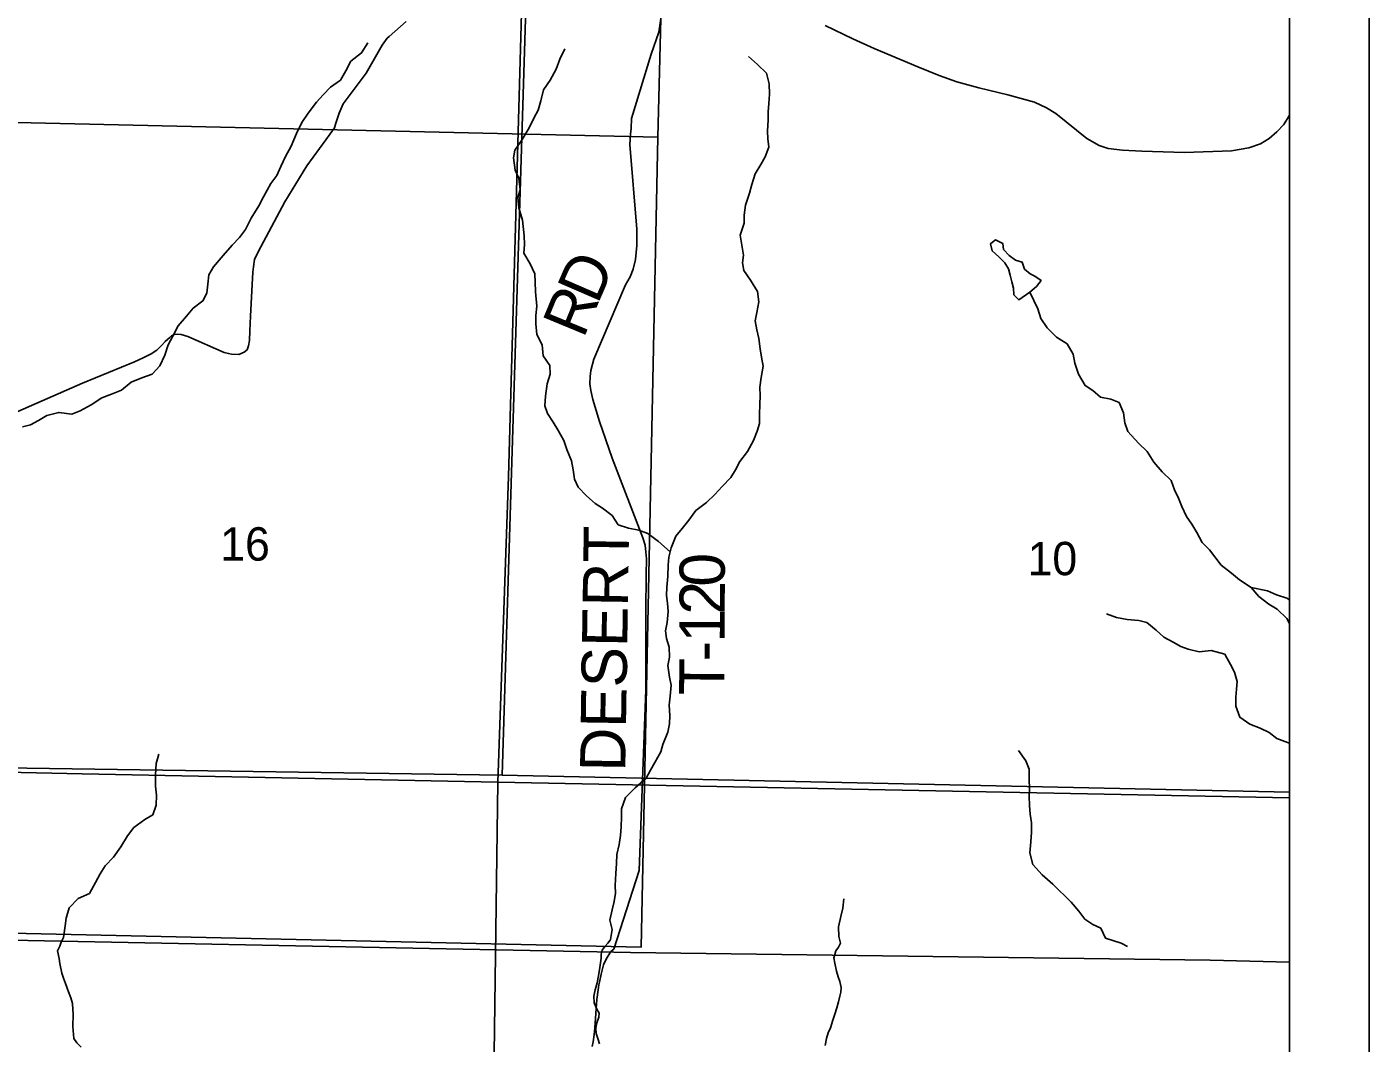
# Model space of a CAD drawing. Extents: x -19.9 to 41.9, y 0 to 32.3.
# Drawn here: x 7.317 to 9, y 17.59 to 18.865 of the extents above; entities that cross this region are included whole.
import ezdxf

# ---------------------------------------------------------------- set-up
doc = ezdxf.new("R2010")
doc.units = 0
for name, color, linetype in [('GM_X_Corporation', 7, 'Continuous'), ('GM_X_County', 7, 'Continuous'), ('GM_X_Minor_Lake', 7, 'Continuous'), ('GM_X_Minor_River', 7, 'Continuous'), ('GM_X_Section', 7, 'Continuous'), ('GM_X_Section_Text', 7, 'Continuous'), ('GM_X_State_Route', 7, 'Continuous'), ('GM_X_Township_Road', 7, 'Continuous'), ('GM_X_Township_Road_Text', 7, 'Continuous'), ('SH_Data', 7, 'Continuous')]:
    doc.layers.add(name, color=color, linetype=linetype)

msp = doc.modelspace()

# ---------------------------------------------------------------- linework, layer by layer
at = {"layer": 'GM_X_Corporation'}
for points in [[(8.9, 17.8974), (8.9, 20.9), (2.1, 20.9), (2.1, 17.918), (2.4715, 17.9106), (2.973, 17.9007), (3.7505, 17.884), (3.984, 17.879), (4.2613, 17.8672), (4.9169, 17.8392), (5.0192, 17.8403), (5.0257, 17.9637), (5.4954, 17.9559), (5.761, 17.9543), (5.9048, 17.9534), (6.2397, 17.9517), (6.2497, 17.9517), (6.3069, 17.9505), (6.7, 17.9422), (6.9468, 17.937), (7.3858, 17.9277), (7.5529, 17.9242), (7.9072, 17.9171)], [(8.9, 17.8974), (8.9, 20.9), (7.9833, 20.9), (7.9567, 19.9408), (7.9433, 19.1981), (7.9387, 18.9418), (7.9208, 18.3004), (7.9072, 17.9171)], [(6.9135, 18.9637), (7.944, 18.9426), (7.9129, 17.9261), (6.8905, 17.9411)], [(8.9, 17.9044), (8.9, 18.9209), (7.944, 18.9426), (7.9129, 17.9261)], [(2.1, 17.918), (2.1, 14.1), (8.9, 14.1), (8.9, 17.8974), (7.9072, 17.9171), (7.5529, 17.9242), (7.3858, 17.9277), (6.9468, 17.937), (6.7, 17.9422), (6.3069, 17.9505), (6.2497, 17.9517), (6.2397, 17.9517), (5.9048, 17.9534), (5.761, 17.9543), (5.4954, 17.9559), (5.0257, 17.9637), (5.0192, 17.8403), (4.9169, 17.8392), (4.2613, 17.8672), (3.984, 17.879), (3.7505, 17.884), (2.973, 17.9007), (2.4715, 17.9106)], [(7.8246, 14.1), (8.9, 14.1), (8.9, 17.8974), (7.9072, 17.9171), (7.9012, 17.4524), (7.8776, 16.5173), (7.8702, 16.1679), (7.854, 15.4058), (7.8518, 15.3043)]]:
    msp.add_lwpolyline(points, close=True, dxfattribs=at)
for points in [[(2.973, 17.9007), (3.7505, 17.884), (3.984, 17.879), (4.2613, 17.8672), (4.9169, 17.8392), (5.0192, 17.8403), (5.0257, 17.9637), (5.4954, 17.9559), (5.761, 17.9543), (5.9048, 17.9534), (6.2397, 17.9517), (6.2497, 17.9517), (6.3069, 17.9505), (6.7, 17.9422), (6.9468, 17.937), (7.3858, 17.9277), (7.5529, 17.9242), (7.9072, 17.9171), (7.9208, 18.3004), (7.9387, 18.9418), (7.9433, 19.1981), (7.9567, 19.9408), (7.9833, 20.9), (2.1, 20.9)], [(7.9012, 17.4524), (7.9072, 17.9171), (7.5529, 17.9242), (7.3858, 17.9277), (6.9468, 17.937), (6.7, 17.9422), (6.3069, 17.9505), (6.2497, 17.9517), (6.2397, 17.9517), (5.9048, 17.9534), (5.761, 17.9543), (5.4954, 17.9559), (5.0257, 17.9637), (5.0192, 17.8403), (4.9169, 17.8392), (4.2613, 17.8672), (3.984, 17.879), (3.7505, 17.884), (2.973, 17.9007), (2.4715, 17.9106), (2.1, 17.918), (2.1, 14.1)]]:
    msp.add_lwpolyline(points, dxfattribs=at)
at = {"layer": 'GM_X_County'}
msp.add_lwpolyline([(8.9, 17.6915), (8.8006, 17.694), (8.0736, 17.7036), (7.0652, 17.7237), (6.7109, 17.7307), (6.5438, 17.7343), (6.1048, 17.7436), (5.8581, 17.7488), (5.4649, 17.757), (5.4078, 17.7582), (5.3977, 17.7582), (5.0628, 17.7599), (4.9191, 17.7608), (4.6534, 17.7624), (4.1838, 17.7703), (4.1772, 17.6468), (4.0749, 17.6457), (3.4193, 17.6737), (3.142, 17.6855), (2.9085, 17.6906), (2.1311, 17.7073), (2.1, 17.7079)], dxfattribs=at)
at = {"layer": 'GM_X_Minor_Lake'}
for points in [[(8.5276, 18.5943), (8.5252, 18.5924), (8.5272, 18.5837), (8.5356, 18.5761), (8.5429, 18.5686), (8.5475, 18.561), (8.5498, 18.5531), (8.5518, 18.5448), (8.5538, 18.5368), (8.5546, 18.5285), (8.5607, 18.5221), (8.5743, 18.5317)], [(8.5743, 18.5317), (8.583, 18.539), (8.5886, 18.5462), (8.5806, 18.5518), (8.5749, 18.5548), (8.5676, 18.5608), (8.5649, 18.5696), (8.5565, 18.5718), (8.5485, 18.5778), (8.5416, 18.5853), (8.5404, 18.5929), (8.5316, 18.5974), (8.5276, 18.5943)], [(8.852, 18.1613), (8.8617, 18.15), (8.8743, 18.1404), (8.8847, 18.1341), (8.8966, 18.1226), (8.9, 18.116)], [(8.9, 18.1458), (8.8969, 18.148), (8.884, 18.152), (8.8725, 18.1571), (8.852, 18.1613)]]:
    msp.add_lwpolyline(points, dxfattribs=at)
at = {"layer": 'GM_X_Minor_River'}
for points in [[(7.3112, 18.3628), (7.3211, 18.3655), (7.3313, 18.3709), (7.3415, 18.3771), (7.3567, 18.381), (7.373, 18.3789), (7.3836, 18.3828), (7.3972, 18.3905), (7.4108, 18.3993), (7.4229, 18.404), (7.4354, 18.4087), (7.4475, 18.419), (7.4608, 18.4241), (7.4736, 18.4291), (7.4834, 18.4394), (7.4898, 18.4528), (7.4938, 18.4657), (7.4998, 18.4764), (7.5062, 18.4894), (7.5167, 18.5016), (7.525, 18.5116), (7.5374, 18.5208), (7.5423, 18.5307), (7.5434, 18.5417), (7.5448, 18.5535), (7.5508, 18.5634), (7.5628, 18.5776), (7.5741, 18.5906), (7.5835, 18.6002), (7.591, 18.6105), (7.5981, 18.6246), (7.6075, 18.6402), (7.6135, 18.6513), (7.6228, 18.6681), (7.6303, 18.678), (7.6352, 18.6894), (7.6411, 18.702), (7.6479, 18.715), (7.6546, 18.7306), (7.6613, 18.7447), (7.6696, 18.7565), (7.6797, 18.7699), (7.6884, 18.7795), (7.6974, 18.7891), (7.7099, 18.7975), (7.7166, 18.8093), (7.7229, 18.8215), (7.7365, 18.8319), (7.7444, 18.8445)], [(8.1233, 18.2059), (8.1086, 18.2189), (8.0956, 18.2291), (8.0841, 18.2331), (8.0712, 18.2357), (8.0582, 18.2401), (8.0506, 18.2515), (8.0387, 18.2608), (8.0292, 18.2665), (8.0184, 18.2762), (8.0081, 18.2872), (8.0035, 18.297), (8.0018, 18.3088), (7.9995, 18.3201), (7.9937, 18.3345), (7.9901, 18.3455), (7.9824, 18.3591), (7.9767, 18.3689), (7.9697, 18.3795), (7.9662, 18.3893), (7.9669, 18.4015), (7.969, 18.4167), (7.9731, 18.4289), (7.9727, 18.4399), (7.9642, 18.452), (7.9629, 18.4656), (7.956, 18.4788), (7.9551, 18.4921), (7.955, 18.5024), (7.9561, 18.5142), (7.9544, 18.532), (7.9539, 18.5445), (7.9535, 18.5548), (7.948, 18.5672), (7.94, 18.5808), (7.9406, 18.5915), (7.9405, 18.6025), (7.9381, 18.6222), (7.9338, 18.6374), (7.9325, 18.6506), (7.9355, 18.6602), (7.9335, 18.6746), (7.9292, 18.6848), (7.9268, 18.7003), (7.9286, 18.7098), (7.938, 18.7232), (7.9466, 18.7377), (7.9526, 18.7499), (7.9578, 18.7602), (7.9612, 18.7716), (7.9645, 18.7857), (7.9731, 18.7975), (7.9806, 18.8113), (7.985, 18.8242), (7.9914, 18.8368)], [(8.0483, 17.719), (8.0485, 17.7199), (8.0506, 17.7323), (8.0479, 17.7441), (8.0508, 17.757), (8.053, 17.7673), (8.0548, 17.7779), (8.0544, 17.7874), (8.0554, 17.8026), (8.056, 17.8152), (8.0567, 17.8262), (8.0596, 17.8391), (8.0611, 17.8501), (8.0621, 17.8612), (8.0624, 17.8737), (8.0623, 17.8836), (8.0675, 17.898), (8.0796, 17.9099), (8.0931, 17.9222), (8.0987, 17.9321), (8.104, 17.942), (8.1115, 17.955), (8.1141, 17.9645), (8.1204, 17.9798), (8.1226, 17.9904), (8.1229, 18.0007), (8.122, 18.0136), (8.1234, 18.025), (8.1245, 18.039), (8.1225, 18.0489), (8.1205, 18.0633), (8.1227, 18.074), (8.1222, 18.0865), (8.119, 18.0975), (8.1174, 18.107), (8.1196, 18.1172), (8.121, 18.1313), (8.1202, 18.1415), (8.119, 18.1514), (8.1193, 18.1617), (8.1203, 18.1757), (8.121, 18.1894), (8.1216, 18.1993), (8.1246, 18.2111), (8.1305, 18.2256), (8.1384, 18.2355), (8.1467, 18.2458), (8.1557, 18.2577), (8.1689, 18.268), (8.1795, 18.278), (8.1885, 18.288), (8.1994, 18.2991), (8.2054, 18.309), (8.2107, 18.3193), (8.2204, 18.3319), (8.2279, 18.3456), (8.2324, 18.3575), (8.2353, 18.367), (8.2356, 18.378), (8.2359, 18.3913), (8.2362, 18.4019), (8.2357, 18.4125), (8.2375, 18.4247), (8.2401, 18.4388), (8.2381, 18.4502), (8.2361, 18.4608), (8.2345, 18.4737), (8.2321, 18.4847), (8.2301, 18.496), (8.2323, 18.5063), (8.2348, 18.5196), (8.2328, 18.5325), (8.224, 18.5469), (8.2159, 18.5589), (8.2143, 18.5684), (8.2154, 18.5783), (8.2134, 18.5908), (8.211, 18.6033), (8.2162, 18.6185), (8.2161, 18.6284), (8.2179, 18.641), (8.2227, 18.6558), (8.226, 18.6668), (8.2301, 18.6802), (8.2372, 18.692), (8.2424, 18.7015), (8.2473, 18.7137), (8.2457, 18.7243), (8.2456, 18.7338), (8.2462, 18.7479), (8.2465, 18.7581), (8.2472, 18.7684), (8.2479, 18.7802), (8.2474, 18.7931), (8.2442, 18.8063), (8.2331, 18.8172), (8.2216, 18.8274)], [(8.7998, 18.2086), (8.7907, 18.2176), (8.7838, 18.2304), (8.7776, 18.2406), (8.7711, 18.2505), (8.7649, 18.2629), (8.7607, 18.2732), (8.756, 18.2837), (8.7517, 18.2955), (8.7403, 18.3064), (8.7299, 18.3185), (8.7218, 18.3317), (8.7107, 18.3422), (8.6973, 18.3569), (8.6934, 18.3679), (8.6918, 18.3804), (8.6864, 18.3933), (8.6761, 18.3977), (8.6631, 18.3999), (8.6536, 18.4086), (8.644, 18.4146), (8.6356, 18.4289), (8.6309, 18.4425), (8.6289, 18.4539), (8.6212, 18.4671), (8.6078, 18.4754), (8.5963, 18.487), (8.5883, 18.4987), (8.5847, 18.5109), (8.5743, 18.5317)], [(8.9, 18.116), (8.8966, 18.1226), (8.8847, 18.1341), (8.8743, 18.1404), (8.8617, 18.15), (8.852, 18.1613), (8.8375, 18.1709), (8.8275, 18.1794), (8.8145, 18.1895), (8.7998, 18.2086)], [(8.8017, 18.0821), (8.7869, 18.0808), (8.7732, 18.0841), (8.7637, 18.0871), (8.7542, 18.0927), (8.7427, 18.0991), (8.7328, 18.1077), (8.7213, 18.1175), (8.711, 18.1201), (8.6966, 18.1211), (8.6833, 18.1236), (8.6707, 18.1284)], [(8.9, 17.9661), (8.8977, 17.967), (8.8843, 17.9721), (8.8744, 17.9795), (8.8633, 17.985), (8.8503, 17.9897), (8.8377, 17.9986), (8.8326, 18.0126), (8.8327, 18.0236), (8.8337, 18.0338), (8.8343, 18.0433), (8.8311, 18.055), (8.826, 18.0648), (8.819, 18.0776), (8.8017, 18.0821)], [(7.3625, 17.7222), (7.3647, 17.7371), (7.3661, 17.7466), (7.3698, 17.7595), (7.3811, 17.771), (7.3951, 17.7776), (7.4029, 17.7913), (7.4086, 17.802), (7.4149, 17.8123), (7.4251, 17.823), (7.4345, 17.836), (7.4427, 17.8498), (7.4506, 17.8601), (7.4646, 17.8705), (7.4748, 17.8763), (7.4789, 17.8881), (7.4791, 17.901), (7.4779, 17.912), (7.4778, 17.9264), (7.4788, 17.9405), (7.4821, 17.9523)], [(8.6968, 17.7109), (8.6892, 17.7151), (8.6695, 17.7213), (8.6633, 17.7338), (8.6534, 17.7387), (8.6434, 17.7454), (8.6358, 17.7552), (8.6262, 17.7665), (8.6032, 17.7891), (8.5898, 17.8008), (8.5783, 17.814), (8.5744, 17.8284), (8.5758, 17.8424), (8.5764, 17.8542), (8.5767, 17.866), (8.5747, 17.877), (8.5739, 17.888), (8.5738, 17.8997), (8.5741, 17.9096), (8.5736, 17.9202), (8.5735, 17.9335), (8.5693, 17.9438), (8.5604, 17.957)], [(8.337, 17.7153), (8.3348, 17.7234), (8.3347, 17.7355), (8.3376, 17.7485), (8.3398, 17.7591), (8.3413, 17.7709)], [(7.3626, 17.6711), (7.3606, 17.6775), (7.3578, 17.6897), (7.357, 17.6958), (7.3549, 17.7056), (7.3578, 17.7112), (7.3596, 17.7165), (7.3625, 17.7222)], [(8.0347, 17.5887), (8.0331, 17.5944), (8.0307, 17.602), (8.0302, 17.6085), (8.0316, 17.6153), (8.0338, 17.6222), (8.0345, 17.6272), (8.0314, 17.6325), (8.0283, 17.6404), (8.0278, 17.6488), (8.0292, 17.6568), (8.0317, 17.6656), (8.0335, 17.674), (8.0352, 17.6847), (8.0369, 17.6962), (8.0369, 17.7015), (8.0383, 17.7065), (8.0414, 17.7111), (8.0453, 17.7153), (8.0483, 17.719)], [(8.3179, 17.5866), (8.3193, 17.5957), (8.3215, 17.6026), (8.3244, 17.6091), (8.3273, 17.6187), (8.3298, 17.626), (8.3324, 17.634), (8.3345, 17.6417), (8.3363, 17.6485), (8.3374, 17.6539), (8.3377, 17.6596), (8.3361, 17.6672), (8.3341, 17.6729), (8.3321, 17.6801), (8.3301, 17.69), (8.3285, 17.6968), (8.3301, 17.7009), (8.331, 17.7054), (8.3344, 17.7101), (8.337, 17.7153)], [(7.3846, 17.5849), (7.3793, 17.5902), (7.3754, 17.5955), (7.3744, 17.6107), (7.3746, 17.6256), (7.3737, 17.6393), (7.3717, 17.6465), (7.3689, 17.654), (7.365, 17.6646), (7.3626, 17.6711)]]:
    msp.add_lwpolyline(points, dxfattribs=at)
at = {"layer": 'GM_X_Section'}
for points in [[(7.1171, 19.7458), (8.1335, 19.7322), (8.1079, 18.7263), (7.1021, 18.7492)], [(7.1021, 18.7492), (8.1079, 18.7263), (8.0871, 17.7103), (7.0709, 17.7326)]]:
    msp.add_lwpolyline(points, close=True, dxfattribs=at)
at = {"layer": 'GM_X_State_Route'}
msp.add_lwpolyline([(8.3176, 18.8663), (8.3524, 18.8495), (8.3791, 18.8374), (8.4339, 18.8146), (8.4609, 18.8036), (8.4828, 18.7957), (8.5106, 18.7879), (8.5469, 18.7791), (8.5804, 18.7702), (8.5954, 18.763), (8.6069, 18.7559), (8.6459, 18.7246), (8.6615, 18.7159), (8.6729, 18.712), (8.6908, 18.7099), (8.715, 18.7088), (8.7685, 18.707), (8.8272, 18.709), (8.8491, 18.713), (8.8636, 18.7177), (8.8744, 18.7244), (8.8844, 18.7327), (8.8932, 18.7422), (8.9, 18.7539)], dxfattribs=at)
at = {"layer": 'GM_X_Township_Road'}
for points in [[(7.292, 18.3762), (7.3866, 18.4176), (7.4516, 18.4443), (7.4627, 18.4494), (7.4725, 18.4543), (7.4797, 18.4592), (7.4862, 18.4656), (7.4899, 18.4699), (7.4936, 18.4727), (7.4958, 18.4749), (7.4982, 18.477), (7.5012, 18.4786), (7.5057, 18.4792), (7.5103, 18.4788), (7.5186, 18.476), (7.564, 18.4562), (7.5695, 18.4548), (7.5732, 18.4541), (7.5825, 18.4535), (7.5891, 18.4564), (7.5928, 18.4596), (7.5947, 18.4643), (7.5958, 18.4712), (7.5963, 18.4834), (7.5973, 18.5016), (7.5992, 18.5414), (7.5999, 18.557), (7.6008, 18.5634), (7.6022, 18.5726), (7.6055, 18.5797), (7.61, 18.5887), (7.6401, 18.6449), (7.6678, 18.6903), (7.6916, 18.7228), (7.7023, 18.738), (7.7043, 18.7438), (7.7085, 18.7564), (7.7135, 18.7678), (7.7422, 18.8065), (7.7622, 18.8415), (7.7685, 18.8503), (7.7709, 18.8526), (7.7923, 18.8711)], [(8.1128, 18.8832), (8.1091, 18.858), (8.0995, 18.8302), (8.0748, 18.7494), (8.0746, 18.7372), (8.0735, 18.73), (8.0727, 18.7171), (8.0818, 18.6107), (8.0818, 18.5901), (8.0798, 18.5727), (8.077, 18.5608), (8.0731, 18.5508), (8.0672, 18.5408), (8.0277, 18.4476), (8.0238, 18.4336), (8.0229, 18.4259), (8.0227, 18.4167), (8.0238, 18.4086), (8.0266, 18.3973), (8.0347, 18.3694), (8.0506, 18.3236), (8.0891, 18.2235), (8.0921, 18.2146), (8.0927, 18.2057), (8.0937, 18.1974), (8.0934, 18.1772), (8.093, 18.132), (8.0927, 18.0328), (8.0844, 17.8065), (8.0528, 17.7075)], [(8.0257, 17.5857), (8.0269, 17.5915), (8.0282, 17.6006), (8.0288, 17.6088), (8.0315, 17.6451), (8.0318, 17.6476), (8.0341, 17.6629), (8.0347, 17.6663), (8.0367, 17.6762), (8.0388, 17.6846), (8.0399, 17.6879), (8.0415, 17.6917), (8.0442, 17.6972), (8.0476, 17.7025), (8.0492, 17.7046), (8.0511, 17.7063), (8.0528, 17.7075)]]:
    msp.add_lwpolyline(points, dxfattribs=at)
at = {"layer": 'SH_Data'}
for p, q in [((9, 21), (9, 14)), ((8.9, 20.9), (8.9, 14.1))]:
    msp.add_line(p, q, dxfattribs=at)

# ---------------------------------------------------------------- texts
at = {"layer": 'GM_X_Section_Text'}
for s, p in [('16', (7.5591, 18.195)), ('10', (8.5716, 18.1767))]:
    msp.add_text(s, height=0.04186, rotation=0, dxfattribs=at).set_placement(p)
at = {"layer": 'GM_X_Township_Road_Text'}
for s, height, rotation, p in [('D', 0.0568, 66.5587, (8.0324, 18.5155)), ('R', 0.0568, 67.5412, (8.0147, 18.4726)), ('DESERT', 0.05682, 89.0972, (8.0671, 17.9301)), ('0', 0.0568, 90.1659, (8.192, 18.1625)), ('2', 0.0568, 89.8678, (8.1919, 18.1271)), ('1', 0.0568, 89.7577, (8.1918, 18.092)), ('-', 0.0568, 89.7351, (8.1916, 18.0687)), ('T', 0.0568, 89.7171, (8.1914, 18.0261))]:
    msp.add_text(s, height=height, rotation=rotation, dxfattribs=at).set_placement(p)

doc.saveas('drawing.dxf')
